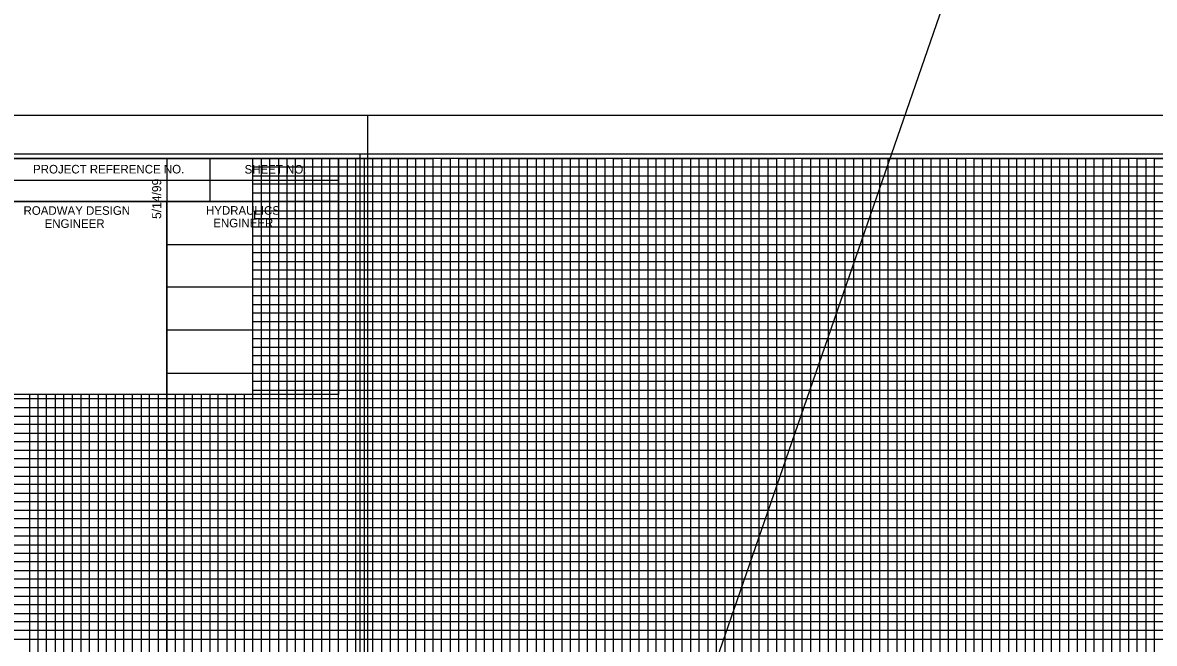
# Model space of a CAD drawing. Extents: x 2345490 to 2436403, y 465165 to 573888.
# Drawn here: x 2413561 to 2414220, y 519225 to 519587 of the extents above; entities that cross this region are included whole.
import ezdxf

# ---------------------------------------------------------------- set-up
doc = ezdxf.new("R2010")
doc.units = 0
for name, color, linetype in [('Old_Level_1', 7, 'Continuous'), ('Old_Level_18', 7, 'Continuous'), ('Old_Level_2', 7, 'Continuous'), ('Old_Level_40', 7, 'Continuous'), ('Old_Level_41', 7, 'Continuous'), ('Old_Level_42', 7, 'Continuous'), ('Old_Level_43', 7, 'Continuous'), ('Old_Level_44', 7, 'Continuous'), ('Old_Level_50', 7, 'Continuous'), ('Old_Level_51', 7, 'Continuous'), ('Old_Level_52', 7, 'Continuous'), ('Old_Level_53', 7, 'Continuous')]:
    doc.layers.add(name, color=color, linetype=linetype)

msp = doc.modelspace()

# ---------------------------------------------------------------- linework, layer by layer
at = {"layer": 'Old_Level_1'}
msp.add_line((2413757.825, 519509.95475), (2413757.825, 519509.95475), dxfattribs=at)
at = {"layer": 'Old_Level_18'}
for points in [[(2413745.325, 519507.40475), (2412245.325, 519507.40475), (2412245.325, 518457.40475), (2413745.325, 518457.40475)], [(2415145.325, 519507.40475), (2413645.325, 519507.40475), (2413645.325, 518457.40475), (2415145.325, 518457.40475)]]:
    msp.add_lwpolyline(points, close=True, dxfattribs=at)
at = {"layer": 'Old_Level_2'}
msp.add_line((2406888.2485, 498751.813), (2414623.19775, 521117.51825), dxfattribs=at)
at = {"layer": 'Old_Level_40'}
for p, q in [((2413670.325, 519507.35475), (2413670.325, 519482.35475)), ((2413545.275, 519494.85475), (2413745.325, 519494.85475)), ((2413645.325, 519482.35475), (2413645.325, 519369.90475))]:
    msp.add_line(p, q, dxfattribs=at)
for points in [[(2413545.275, 519507.40475), (2413745.325, 519507.40475), (2413745.325, 519482.35475), (2413545.275, 519482.35475)], [(2413545.275, 519482.35475), (2413645.325, 519482.35475), (2413645.325, 519369.85475), (2413545.275, 519369.85475)], [(2413645.325, 519482.35475), (2413745.325, 519482.35475), (2413745.325, 519369.85475), (2413645.325, 519369.85475)]]:
    msp.add_lwpolyline(points, close=True, dxfattribs=at)
at = {"layer": 'Old_Level_41'}
for points in [[(2413545.325, 519507.40475), (2413571.625, 519507.40475)], [(2413645.325, 519507.40475), (2413695.325, 519507.40475), (2413695.325, 518482.40475), (2413745.325, 518482.40475), (2413745.325, 519507.40475), (2413795.325, 519507.40475), (2413795.325, 518482.40475), (2413845.325, 518482.40475), (2413845.325, 519507.40475), (2413895.325, 519507.40475), (2413895.325, 518482.40475), (2413945.325, 518482.40475), (2413945.325, 519507.40475), (2413995.325, 519507.40475), (2413995.325, 518482.40475), (2414045.325, 518482.40475), (2414045.325, 519507.40475), (2414095.325, 519507.40475), (2414095.325, 518482.40475), (2414145.325, 518482.40475), (2414145.325, 519507.40475), (2414195.325, 519507.40475), (2414195.325, 518482.40475), (2414245.325, 518482.40475)], [(2413720.325, 518482.40475), (2413720.325, 519507.40475), (2413770.325, 519507.40475), (2413770.325, 518482.40475), (2413820.325, 518482.40475), (2413820.325, 519507.40475), (2413870.325, 519507.40475), (2413870.325, 518482.40475), (2413920.325, 518482.40475), (2413920.325, 519507.40475), (2413970.325, 519507.40475), (2413970.325, 518482.40475), (2414020.325, 518482.40475), (2414020.325, 519507.40475), (2414070.325, 519507.40475), (2414070.325, 518482.40475), (2414120.325, 518482.40475), (2414120.325, 519507.40475), (2414170.325, 519507.40475), (2414170.325, 518482.40475), (2414220.325, 518482.40475), (2414220.325, 519507.40475), (2414270.325, 519507.40475)], [(2413645.325, 519457.40475), (2414945.275, 519457.40475)], [(2413545.275, 519407.40475), (2412245.325, 519407.40475), (2412245.325, 519357.35475), (2413745.325, 519357.35475)], [(2414945.275, 519407.40475), (2413645.325, 519407.40475), (2413645.325, 519357.35475), (2415145.325, 519357.35475)], [(2413745.325, 519332.40475), (2412245.325, 519332.40475), (2412245.325, 519382.40475), (2413545.275, 519382.40475)], [(2415145.325, 519332.40475), (2413645.325, 519332.40475), (2413645.325, 519382.40475), (2414945.275, 519382.40475)], [(2413570.325, 519369.85475), (2413570.325, 518482.40475), (2413620.325, 518482.40475), (2413620.325, 519369.85475)], [(2413670.325, 519369.85475), (2413670.325, 518482.40475)], [(2413745.325, 519307.40475), (2412245.325, 519307.40475), (2412245.325, 519257.40475), (2413745.325, 519257.40475)], [(2415145.325, 519307.40475), (2413645.325, 519307.40475), (2413645.325, 519257.40475), (2415145.325, 519257.40475)], [(2413745.325, 519232.40475), (2412245.325, 519232.40475), (2412245.325, 519282.40475), (2413745.325, 519282.40475)], [(2415145.325, 519232.40475), (2413645.325, 519232.40475), (2413645.325, 519282.40475), (2415145.325, 519282.40475)]]:
    msp.add_lwpolyline(points, dxfattribs=at)
at = {"layer": 'Old_Level_42'}
for points in [[(2414945.275, 519432.40475), (2413645.425, 519432.40475), (2413645.425, 519482.35475), (2414945.275, 519482.35475)], [(2413595.325, 519369.85475), (2413595.325, 518482.40475), (2413645.325, 518482.40475), (2413645.325, 519369.85475)], [(2413695.325, 519369.85475), (2413695.325, 518482.40475), (2413745.325, 518482.40475)]]:
    msp.add_lwpolyline(points, dxfattribs=at)
at = {"layer": 'Old_Level_43'}
for p, q in [((2413695.325, 519327.40475), (2412295.325, 519327.40475)), ((2415095.325, 519327.40475), (2413695.325, 519327.40475)), ((2413695.325, 519327.40475), (2413695.325, 519322.40475)), ((2412295.325, 519322.40475), (2413695.325, 519322.40475)), ((2413695.325, 519322.40475), (2415095.325, 519322.40475)), ((2413695.325, 519302.40475), (2412295.325, 519302.40475)), ((2415095.325, 519302.40475), (2413695.325, 519302.40475))]:
    msp.add_line(p, q, dxfattribs=at)
for points in [[(2413700.325, 519507.40475), (2413705.325, 519507.40475), (2413710.325, 519507.40475), (2413715.325, 519507.40475), (2413725.325, 519507.40475), (2413692.275, 519507.40475), (2413697.275, 519507.40475), (2413655.325, 519507.40475), (2413660.325, 519507.40475), (2413665.325, 519507.40475), (2413675.325, 519507.40475), (2413680.325, 519507.40475), (2413685.325, 519507.40475), (2413690.325, 519507.40475), (2413700.325, 519507.40475), (2413700.325, 518482.40475)], [(2413705.325, 518482.40475), (2413705.325, 519507.40475), (2413710.325, 519507.40475), (2413710.325, 518482.40475)], [(2413715.325, 518482.40475), (2413715.325, 519507.40475), (2413725.325, 519507.40475), (2413725.325, 518482.40475)], [(2413730.325, 518482.40475), (2413730.325, 519507.40475), (2413735.325, 519507.40475), (2413735.325, 518482.40475)], [(2413740.325, 518482.40475), (2413740.325, 519507.40475), (2413750.325, 519507.40475), (2413750.325, 518482.40475)], [(2413755.325, 518482.40475), (2413755.325, 519507.40475), (2413760.325, 519507.40475), (2413760.325, 518482.40475)], [(2413765.325, 518482.40475), (2413765.325, 519507.40475), (2413775.325, 519507.40475), (2413775.325, 518482.40475)], [(2413780.325, 518482.40475), (2413780.325, 519507.40475), (2413785.325, 519507.40475), (2413785.325, 518482.40475)], [(2413790.325, 518482.40475), (2413790.325, 519507.40475), (2413800.325, 519507.40475), (2413800.325, 518482.40475)], [(2413805.325, 518482.40475), (2413805.325, 519507.40475), (2413810.325, 519507.40475), (2413810.325, 518482.40475)], [(2413815.325, 518482.40475), (2413815.325, 519507.40475), (2413825.325, 519507.40475), (2413825.325, 518482.40475)], [(2413830.325, 518482.40475), (2413830.325, 519507.40475), (2413835.325, 519507.40475), (2413835.325, 518482.40475)], [(2413840.325, 518482.40475), (2413840.325, 519507.40475), (2413850.325, 519507.40475), (2413850.325, 518482.40475)], [(2413855.325, 518482.40475), (2413855.325, 519507.40475), (2413860.325, 519507.40475), (2413860.325, 518482.40475)], [(2413865.325, 518482.40475), (2413865.325, 519507.40475), (2413875.325, 519507.40475), (2413875.325, 518482.40475)], [(2413880.325, 518482.40475), (2413880.325, 519507.40475), (2413885.325, 519507.40475), (2413885.325, 518482.40475)], [(2413890.325, 518482.40475), (2413890.325, 519507.40475), (2413900.325, 519507.40475), (2413900.325, 518482.40475)], [(2413905.325, 518482.40475), (2413905.325, 519507.40475), (2413905.325, 519507.40475), (2413910.325, 519507.40475), (2413910.325, 518482.40475)], [(2413915.325, 518482.40475), (2413915.325, 519507.40475), (2413925.325, 519507.40475), (2413925.325, 518482.40475)], [(2413930.325, 518482.40475), (2413930.325, 519507.40475), (2413935.325, 519507.40475), (2413935.325, 518482.40475)], [(2413940.325, 518482.40475), (2413940.325, 519507.40475), (2413950.325, 519507.40475), (2413950.325, 518482.40475)], [(2413955.325, 518482.40475), (2413955.325, 519507.40475), (2413960.325, 519507.40475), (2413960.325, 518482.40475)], [(2413965.325, 518482.40475), (2413965.325, 519507.40475), (2413975.325, 519507.40475), (2413975.325, 518482.40475)], [(2413980.325, 518482.40475), (2413980.325, 519507.40475), (2413985.325, 519507.40475), (2413985.325, 518482.40475)], [(2413990.325, 518482.40475), (2413990.325, 519507.40475), (2414000.325, 519507.40475), (2414000.325, 518482.40475)], [(2414005.325, 518482.40475), (2414005.325, 519507.40475), (2414010.325, 519507.40475), (2414010.325, 518482.40475)], [(2414015.325, 518482.40475), (2414015.325, 519507.40475), (2414025.325, 519507.40475), (2414025.325, 518482.40475)], [(2414030.325, 519507.40475), (2414030.325, 518482.40475), (2414035.325, 518482.40475), (2414035.325, 519507.40475)], [(2414030.325, 519506.80475), (2414030.325, 518482.40475), (2414035.325, 518482.40475), (2414035.325, 519506.80475)], [(2414040.325, 518482.40475), (2414040.325, 519507.40475), (2414050.325, 519507.40475), (2414050.325, 518482.40475)], [(2414055.325, 518482.40475), (2414055.325, 519507.40475), (2414060.325, 519507.40475), (2414060.325, 518482.40475)], [(2414065.325, 518482.40475), (2414065.325, 519507.40475), (2414075.325, 519507.40475), (2414075.325, 518482.40475)], [(2414080.325, 518482.40475), (2414080.325, 519507.40475), (2414085.325, 519507.40475), (2414085.325, 518482.40475)], [(2414090.325, 518482.40475), (2414090.325, 519507.40475), (2414100.325, 519507.40475), (2414100.325, 518482.40475)], [(2414105.325, 518482.40475), (2414105.325, 519507.40475), (2414110.325, 519507.40475), (2414110.325, 518482.40475)], [(2414115.325, 518482.40475), (2414115.325, 519507.40475), (2414125.325, 519507.40475), (2414125.325, 518482.40475)], [(2414130.325, 518482.40475), (2414130.325, 519507.40475), (2414135.325, 519507.40475), (2414135.325, 518482.40475)], [(2414140.325, 518482.40475), (2414140.325, 519507.40475), (2414150.325, 519507.40475), (2414150.325, 518482.40475)], [(2414155.325, 518482.40475), (2414155.325, 519507.40475), (2414160.325, 519507.40475), (2414160.325, 518482.40475)], [(2414165.325, 518482.40475), (2414165.325, 519507.40475), (2414175.325, 519507.40475), (2414175.325, 518482.40475)], [(2414180.325, 519507.40475), (2414180.325, 518482.40475), (2414185.325, 518482.40475), (2414185.325, 519507.40475), (2414190.325, 519507.40475), (2414190.325, 518482.40475), (2414200.325, 518482.40475), (2414200.325, 519507.40475), (2414205.325, 519507.40475), (2414205.325, 518482.40475), (2414210.325, 518482.40475), (2414210.325, 519507.40475), (2414215.325, 519507.40475), (2414215.325, 518482.40475)], [(2414945.275, 519502.40475), (2413695.325, 519502.40475), (2413695.325, 519497.40475), (2414945.275, 519497.40475)], [(2414945.275, 519492.40475), (2413695.325, 519492.40475), (2413695.325, 519487.40475), (2414945.275, 519487.40475)], [(2414945.275, 519476.65475), (2413696.325, 519476.65475), (2413696.325, 519472.40475), (2414945.275, 519472.40475)], [(2414945.275, 519467.40475), (2413695.325, 519467.40475), (2413695.325, 519462.40475), (2414945.275, 519462.40475)], [(2414945.275, 519452.40475), (2413695.325, 519452.40475), (2413695.325, 519447.40475), (2414945.275, 519447.40475)], [(2414945.275, 519442.40475), (2413695.325, 519442.40475), (2413695.325, 519437.40475), (2414945.275, 519437.40475)], [(2414945.275, 519427.40475), (2413695.325, 519427.40475), (2413695.325, 519422.40475), (2414945.275, 519422.40475)], [(2414945.275, 519417.40475), (2413695.325, 519417.40475), (2413695.325, 519412.40475), (2414945.275, 519412.40475)], [(2414945.275, 519402.40475), (2413695.325, 519402.40475), (2413695.325, 519397.40475), (2414945.275, 519397.40475)], [(2414945.275, 519392.40475), (2413695.325, 519392.40475), (2413695.325, 519387.40475), (2414945.275, 519387.40475)], [(2414945.275, 519377.40475), (2413695.325, 519377.40475), (2413695.325, 519372.40475), (2414945.275, 519372.40475)], [(2413695.325, 519367.40475), (2412295.325, 519367.40475), (2412295.325, 519367.40475), (2412295.325, 519347.40475), (2413695.325, 519347.40475)], [(2413565.325, 519369.85475), (2413565.325, 518482.40475), (2413575.325, 518482.40475), (2413575.325, 519369.85475)], [(2413580.325, 519369.85475), (2413580.325, 518482.40475), (2413585.325, 518482.40475), (2413585.325, 519369.85475)], [(2413590.325, 519369.85475), (2413590.325, 518482.40475), (2413600.325, 518482.40475), (2413600.325, 519369.85475)], [(2413605.325, 519369.85475), (2413605.325, 518482.40475), (2413610.325, 518482.40475), (2413610.325, 519369.85475)], [(2413615.325, 519369.85475), (2413615.325, 518482.40475), (2413625.325, 518482.40475), (2413625.325, 519369.85475)], [(2413630.325, 519369.85475), (2413630.325, 518482.40475)], [(2413630.325, 518482.40475), (2413635.325, 518482.40475), (2413635.325, 519369.85475)], [(2413640.325, 519369.85475), (2413640.325, 518482.40475), (2413650.325, 518482.40475), (2413650.325, 519369.85475)], [(2413655.325, 519369.85475), (2413655.325, 518482.40475), (2413660.325, 518482.40475), (2413660.325, 519369.85475)], [(2413665.325, 519369.85475), (2413665.325, 518482.40475), (2413675.325, 518482.40475), (2413675.325, 519369.85475)], [(2413680.325, 519369.85475), (2413680.325, 518482.40475), (2413685.325, 518482.40475), (2413685.325, 519369.85475)], [(2413690.325, 519369.85475), (2413690.325, 518482.40475), (2413700.325, 518482.40475)], [(2415095.325, 519367.40475), (2413695.325, 519367.40475), (2413695.325, 519367.40475), (2413695.325, 519347.40475), (2415095.325, 519347.40475)], [(2412295.325, 519362.40475), (2413695.325, 519362.40475)], [(2413695.325, 519362.40475), (2415095.325, 519362.40475)], [(2413695.325, 519352.40475), (2412295.325, 519352.40475)], [(2415095.325, 519352.40475), (2413695.325, 519352.40475)], [(2413695.325, 519342.40475), (2412295.325, 519342.40475), (2412295.325, 519337.40475), (2413695.325, 519337.40475)], [(2415095.325, 519342.40475), (2413695.325, 519342.40475), (2413695.325, 519337.40475), (2415095.325, 519337.40475)], [(2413695.325, 519317.40475), (2412295.325, 519317.40475), (2412295.325, 519312.40475), (2413695.325, 519312.40475)], [(2415095.325, 519317.40475), (2413695.325, 519317.40475), (2413695.325, 519312.40475), (2415095.325, 519312.40475)], [(2413695.325, 519297.40475), (2412295.325, 519297.40475), (2412295.325, 519292.40475), (2413695.325, 519292.40475)], [(2415095.325, 519297.40475), (2413695.325, 519297.40475), (2413695.325, 519292.40475), (2415095.325, 519292.40475)], [(2413695.325, 519287.40475), (2412295.325, 519287.40475)], [(2415095.325, 519287.40475), (2413695.325, 519287.40475)], [(2412295.325, 519277.40475), (2413695.325, 519277.40475)], [(2413695.325, 519277.40475), (2415095.325, 519277.40475)], [(2413695.325, 519272.40475), (2412295.325, 519272.40475), (2412295.325, 519267.40475), (2413695.325, 519267.40475)], [(2415095.325, 519272.40475), (2413695.325, 519272.40475), (2413695.325, 519267.40475), (2415095.325, 519267.40475)], [(2413695.325, 519262.40475), (2412295.325, 519262.40475), (2412295.325, 519252.40475), (2413695.325, 519252.40475)], [(2415095.325, 519262.40475), (2413695.325, 519262.40475), (2413695.325, 519252.40475), (2415095.325, 519252.40475)], [(2413695.325, 519247.40475), (2412295.325, 519247.40475), (2412295.325, 519242.40475), (2413695.325, 519242.40475)], [(2415095.325, 519247.40475), (2413695.325, 519247.40475), (2413695.325, 519242.40475), (2415095.325, 519242.40475)], [(2413695.325, 519237.40475), (2412295.325, 519237.40475), (2412295.325, 519227.40475), (2413695.325, 519227.40475)], [(2415095.325, 519237.40475), (2413695.325, 519237.40475), (2413695.325, 519227.40475), (2415095.325, 519227.40475)]]:
    msp.add_lwpolyline(points, dxfattribs=at)
at = {"layer": 'Old_Level_50'}
msp.add_line((2413762.325, 519532.40475), (2413762.325, 519532.40475), dxfattribs=at)
for points in [[(2413757.825, 519509.95475), (2412091.325, 519509.95475), (2412091.325, 518454.85475), (2413757.825, 518454.85475)], [(2415157.825, 519509.95475), (2413491.325, 519509.95475), (2413491.325, 518454.85475), (2415157.825, 518454.85475)]]:
    msp.add_lwpolyline(points, close=True, dxfattribs=at)
at = {"layer": 'Old_Level_51'}
for points in [[(2413762.325, 519532.40475), (2412078.325, 519532.40475), (2412078.325, 518432.40475), (2413762.325, 518432.40475)], [(2415162.325, 519532.40475), (2413478.325, 519532.40475), (2413478.325, 518432.40475), (2415162.325, 518432.40475)]]:
    msp.add_lwpolyline(points, close=True, dxfattribs=at)
at = {"layer": 'Old_Level_52'}
msp.add_line((2413757.825, 519509.95475), (2413757.825, 519509.95475), dxfattribs=at)
at = {"layer": 'Old_Level_53'}
msp.add_line((2413757.825, 519509.95475), (2413757.825, 519509.95475), dxfattribs=at)

# ---------------------------------------------------------------- texts
at = {"layer": 'Old_Level_41'}
msp.add_text('5/14/99', height=5.25, rotation=90, dxfattribs=at).set_placement((2413642.075, 519472.20475))
at = {"layer": 'Old_Level_44'}
for s, p in [('PROJECT REFERENCE NO.', (2413567.475, 519498.70475)), ('SHEET NO.', (2413690.625, 519498.60475)), ('ROADWAY DESIGN', (2413561.925, 519474.60475)), ('HYDRAULICS', (2413668.125, 519474.65475)), ('ENGINEER', (2413574.175, 519467.00475)), ('ENGINEER', (2413672.375, 519467.30475))]:
    msp.add_text(s, height=5.0001, dxfattribs=at).set_placement(p)

doc.saveas('drawing.dxf')
